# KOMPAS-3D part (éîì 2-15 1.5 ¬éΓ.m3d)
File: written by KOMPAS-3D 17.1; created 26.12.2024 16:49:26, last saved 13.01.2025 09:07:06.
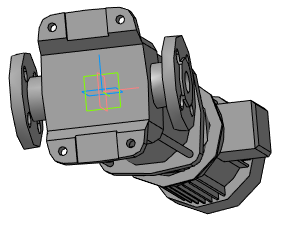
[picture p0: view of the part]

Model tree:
1. Операция без истории:4  (labels: ВМН 2-15 1.5 кВт)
